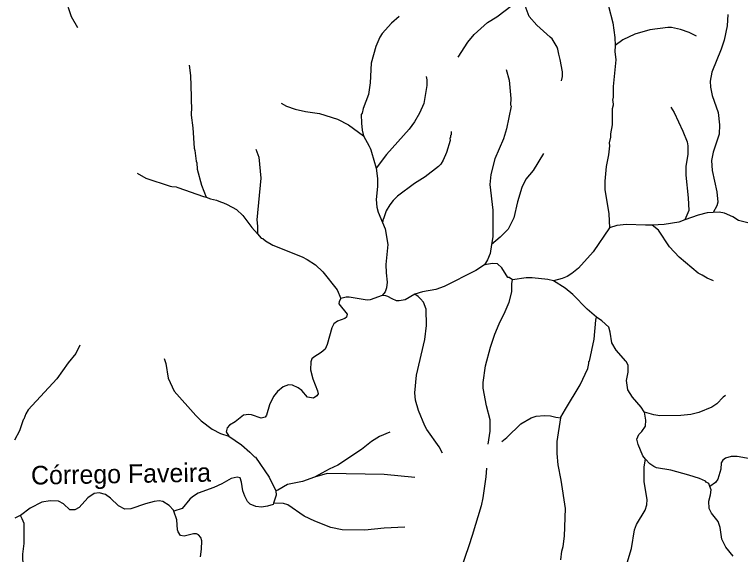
# Model space of a CAD drawing. Extents: x 280.4 to 335.6, y 8893.9 to 8949.5.
# Drawn here: x 280.62 to 288.41, y 8917.81 to 8923.61 of the extents above; entities that cross this region are included whole.
import ezdxf
from ezdxf.enums import TextEntityAlignment as Align

# ---------------------------------------------------------------- set-up
doc = ezdxf.new("R2010")
doc.units = 0
doc.header["$LTSCALE"] = 0.064
doc.linetypes.add('LONG_DASHED', pattern=[7.5, 6, -1.5])
doc.layers.add('61', color=7, linetype='Continuous')
doc.layers.add('7', color=7, linetype='Continuous', lineweight=25)
doc.layers.add('9', color=7, linetype='LONG_DASHED', lineweight=25)

msp = doc.modelspace()

# ---------------------------------------------------------------- linework, layer by layer
at = {"layer": '7'}
for points in [[(285.3795, 8923.1514), (285.4805, 8923.3118), (285.5493, 8923.3936), (285.6944, 8923.5227), (285.7934, 8923.5852), (285.957, 8923.7103), (285.9929, 8923.7477), (286.0681, 8923.8523)], [(286.4884, 8922.8963), (286.4998, 8922.9429), (286.4987, 8922.9917), (286.4747, 8923.1261), (286.46, 8923.1839), (286.4488, 8923.2373), (286.4425, 8923.2565), (286.3867, 8923.346), (286.3675, 8923.366), (286.2226, 8923.4934), (286.1417, 8923.5874), (286.1072, 8923.6723), (286.0681, 8923.8523)], [(286.9295, 8923.8274), (286.9929, 8923.6986), (287.0406, 8923.5202), (287.06, 8923.3621), (287.0645, 8923.2748)], [(284.7434, 8923.587), (284.6639, 8923.5158), (284.5625, 8923.4033), (284.5362, 8923.3654), (284.4934, 8923.2636), (284.4455, 8923.0851), (284.4339, 8922.8753), (284.4147, 8922.7488), (284.3572, 8922.6009), (284.3477, 8922.551), (284.3387, 8922.5336), (284.3395, 8922.4408), (284.3478, 8922.3681), (284.3631, 8922.3063)], [(288.2741, 8923.608), (288.2674, 8923.4875), (288.2332, 8923.3318), (288.2016, 8923.2374), (288.1004, 8922.9907), (288.0838, 8922.8933), (288.0885, 8922.8279), (288.1061, 8922.7385), (288.1697, 8922.5574), (288.1827, 8922.4231), (288.1793, 8922.3248), (288.1148, 8922.1289), (288.0964, 8922.0411), (288.1041, 8921.9323), (288.1571, 8921.7059), (288.1665, 8921.5955), (288.1568, 8921.5543), (288.1175, 8921.4842)], [(287.9374, 8923.3758), (287.8584, 8923.4145), (287.7644, 8923.4488), (287.6691, 8923.4697), (287.6295, 8923.4699), (287.4343, 8923.4427), (287.2759, 8923.3968), (287.1479, 8923.3365), (287.0645, 8923.2748)], [(287.0645, 8923.2748), (287.0646, 8923.2734), (287.0602, 8923.2125), (287.0696, 8923.1229), (287.0441, 8922.835), (287.0425, 8922.7215), (287.0345, 8922.6873), (287.0393, 8922.6815), (287.0409, 8922.6337), (287.033, 8922.5975), (287.0328, 8922.4224), (287.0154, 8922.3271), (287.0147, 8922.2917), (286.9995, 8922.2298), (287.0024, 8922.1978), (286.9929, 8922.1034), (286.9675, 8921.9753), (286.9546, 8921.8187), (286.9546, 8921.7291), (286.9947, 8921.4677), (287.0024, 8921.3169)], [(282.4913, 8923.0641), (282.5053, 8922.9541), (282.5133, 8922.7295), (282.5102, 8922.6726), (282.5165, 8922.6175), (282.5118, 8922.5288), (282.5309, 8922.3929), (282.5451, 8922.1722), (282.553, 8922.148), (282.5649, 8922.0348), (282.5725, 8922.0169), (282.5759, 8921.9491), (282.6236, 8921.7771), (282.6734, 8921.6463)], [(285.8953, 8923.0168), (285.9244, 8922.9028), (285.9438, 8922.7061), (285.9405, 8922.639), (285.9465, 8922.6252), (285.8976, 8922.3814), (285.8651, 8922.2748), (285.7728, 8922.0589), (285.728, 8921.8922), (285.7167, 8921.7852), (285.7517, 8921.5061), (285.7517, 8921.2222), (285.7379, 8921.1397)], [(285.0349, 8922.9427), (285.0434, 8922.9085), (285.0418, 8922.8453), (285.0114, 8922.6538), (284.9624, 8922.5499), (284.9081, 8922.4555), (284.851, 8922.3786), (284.6106, 8922.1042), (284.4986, 8921.958)], [(283.4773, 8922.6553), (283.5363, 8922.6238), (283.6274, 8922.5937), (283.7407, 8922.5663), (283.889, 8922.5458), (284.0832, 8922.4835), (284.2, 8922.4259), (284.3631, 8922.3063)], [(287.6623, 8922.6136), (287.6968, 8922.5561), (287.7912, 8922.3546), (287.8357, 8922.2433), (287.8454, 8922.1978), (287.8437, 8922.1096), (287.8217, 8921.9771), (287.8214, 8921.8851), (287.8469, 8921.6388), (287.8533, 8921.5059), (287.8129, 8921.4034)], [(285.3048, 8922.354), (285.3037, 8922.3161), (285.2977, 8922.3112), (285.2974, 8922.2884), (285.2898, 8922.2818), (285.2911, 8922.2551), (285.2529, 8922.1281), (285.2183, 8922.0464), (285.1908, 8922.0003), (285.1677, 8921.975), (285.0253, 8921.8656), (284.9096, 8921.7927), (284.7278, 8921.6576), (284.6788, 8921.6116), (284.6439, 8921.5658), (284.6069, 8921.5012), (284.578, 8921.4142), (284.5715, 8921.4136), (284.5672, 8921.3752)], [(284.3631, 8922.3063), (284.4223, 8922.1964), (284.4329, 8922.1748), (284.4405, 8922.1544), (284.447, 8922.1323), (284.4986, 8921.958)], [(283.2076, 8922.1615), (283.2391, 8922.0785), (283.2585, 8921.8531), (283.2171, 8921.4046), (283.225, 8921.3374), (283.2251, 8921.2531)], [(286.2959, 8922.1147), (286.184, 8921.9336), (286.1051, 8921.8397), (286.0635, 8921.7517), (286.0164, 8921.597), (285.9771, 8921.4271), (285.9145, 8921.3024), (285.8306, 8921.2169), (285.7379, 8921.1397)], [(284.4986, 8921.958), (284.5108, 8921.8483), (284.5108, 8921.7604), (284.4982, 8921.6225), (284.5067, 8921.5417), (284.5198, 8921.4857), (284.5672, 8921.3752)], [(281.9322, 8921.9066), (282.0236, 8921.852), (282.2881, 8921.7672), (282.3047, 8921.7636), (282.3517, 8921.7571), (282.3694, 8921.7523), (282.6456, 8921.6534), (282.6734, 8921.6463)], [(282.6734, 8921.6463), (282.7212, 8921.6313), (282.7852, 8921.6137), (282.8281, 8921.5985), (282.8588, 8921.5854), (282.8966, 8921.5685), (282.9985, 8921.5135), (283.0651, 8921.4516), (283.1642, 8921.3234), (283.2251, 8921.2531)], [(288.1175, 8921.4842), (288.0509, 8921.4802), (287.9557, 8921.4548), (287.8129, 8921.4034)], [(288.4882, 8921.3735), (288.3874, 8921.3983), (288.3264, 8921.4365), (288.2375, 8921.4765), (288.181, 8921.488), (288.1175, 8921.4842)], [(287.8129, 8921.4034), (287.747, 8921.3796), (287.5885, 8921.3527), (287.4604, 8921.3485)], [(284.5672, 8921.3752), (284.5961, 8921.3078), (284.6227, 8921.1382), (284.6005, 8920.923), (284.6037, 8920.8335), (284.6178, 8920.7356), (284.6101, 8920.6726), (284.5936, 8920.6315), (284.563, 8920.59)], [(287.0024, 8921.3169), (286.8286, 8921.0588), (286.669, 8920.8845), (286.6004, 8920.8275), (286.5489, 8920.7948), (286.4934, 8920.7729), (286.4015, 8920.7489)], [(287.4604, 8921.3485), (287.3888, 8921.3462), (287.1841, 8921.3541), (287.0832, 8921.3446), (287.0024, 8921.3169)], [(288.1212, 8920.7487), (288.0511, 8920.778), (287.9969, 8920.8091), (287.9551, 8920.8331), (287.7515, 8921.0019), (287.6459, 8921.1152), (287.5297, 8921.292), (287.4604, 8921.3485)], [(283.2251, 8921.2531), (283.2644, 8921.2078), (283.2819, 8921.2022), (283.31, 8921.1793), (283.3891, 8921.1331), (283.7023, 8921.0084), (283.7586, 8920.9787), (283.8455, 8920.9207), (283.9266, 8920.8445), (284.0787, 8920.6509), (284.12, 8920.56)], [(285.7379, 8921.1397), (285.7215, 8921.0412), (285.6939, 8920.976), (285.6616, 8920.9215)], [(285.6616, 8920.9215), (285.5688, 8920.8583), (285.228, 8920.6892), (285.1402, 8920.6567), (284.997, 8920.6296), (284.914, 8920.6054)], [(285.9616, 8920.7609), (285.9257, 8920.7834), (285.911, 8920.7861), (285.8462, 8920.8903), (285.7998, 8920.9306), (285.7454, 8920.9366), (285.6616, 8920.9215)], [(286.4015, 8920.7489), (286.3404, 8920.7626), (286.1715, 8920.7815), (286.109, 8920.7796), (285.9616, 8920.7609)], [(285.6989, 8918.9958), (285.7225, 8919.1335), (285.7231, 8919.2564), (285.6814, 8919.4069), (285.6464, 8919.5982), (285.6464, 8919.6572), (285.6708, 8919.837), (285.7256, 8920.0372), (285.7715, 8920.1753), (285.8169, 8920.2876), (285.8837, 8920.42), (285.9263, 8920.52), (285.9532, 8920.6312), (285.9535, 8920.7215), (285.9616, 8920.7609)], [(286.8634, 8920.3602), (286.7621, 8920.4462), (286.6106, 8920.604), (286.5275, 8920.6712), (286.4015, 8920.7489)], [(284.12, 8920.56), (284.1024, 8920.5272), (284.097, 8920.5004), (284.1859, 8920.3903), (284.1788, 8920.3579), (284.1623, 8920.346), (284.0816, 8920.3143), (284.0441, 8920.2872), (284.0221, 8920.2461), (283.9717, 8920.0644), (283.9492, 8920.0141), (283.9089, 8919.9795), (283.8285, 8919.9313), (283.809, 8919.9101), (283.7958, 8919.8788), (283.793, 8919.7925), (283.8198, 8919.6981), (283.8696, 8919.5686)], [(284.563, 8920.59), (284.4328, 8920.5439), (284.4029, 8920.5419), (284.2094, 8920.5737), (284.1774, 8920.5735), (284.12, 8920.56)], [(284.914, 8920.6054), (284.8095, 8920.5454), (284.7455, 8920.5336), (284.7157, 8920.5356), (284.6713, 8920.5559), (284.6245, 8920.5808), (284.6009, 8920.589), (284.563, 8920.59)], [(285.2095, 8918.8995), (285.1739, 8918.9657), (285.0412, 8919.1522), (285.0203, 8919.1906), (284.9536, 8919.3559), (284.9202, 8919.4678), (284.914, 8919.5455), (284.9298, 8919.7348), (285.0194, 8920.1196), (285.0385, 8920.2713), (285.0339, 8920.4434), (285.0079, 8920.5183), (284.9751, 8920.5572), (284.9474, 8920.5818), (284.914, 8920.6054)], [(286.4791, 8919.2786), (286.4802, 8919.2859), (286.532, 8919.3727), (286.6874, 8919.6334), (286.7689, 8919.8096), (286.7815, 8919.8629), (286.7804, 8919.8819), (286.7884, 8919.8864), (286.8392, 8920.122), (286.8554, 8920.3267), (286.8634, 8920.3602)], [(287.3776, 8919.338), (287.3769, 8919.3418), (287.3441, 8919.3939), (287.2515, 8919.4997), (287.201, 8919.5782), (287.1864, 8919.6787), (287.204, 8919.7684), (287.202, 8919.845), (287.1815, 8919.8828), (287.1785, 8919.8862), (287.0735, 8920.0047), (287.028, 8920.0851), (287.0105, 8920.1987), (286.9958, 8920.2505), (286.9225, 8920.3194), (286.8634, 8920.3602)], [(281.3157, 8920.0598), (281.272, 8919.9678), (281.1905, 8919.867), (281.0683, 8919.6979), (280.7602, 8919.3639), (280.7357, 8919.3209), (280.7171, 8919.2636), (280.7074, 8919.2577), (280.6678, 8919.1375), (280.6154, 8919.0369)], [(282.2234, 8919.9155), (282.2399, 8919.8605), (282.2665, 8919.7036), (282.3305, 8919.5653), (282.5602, 8919.3033), (282.6177, 8919.2473), (282.7384, 8919.1566), (282.8259, 8919.1117), (282.9163, 8919.08)], [(283.8696, 8919.5686), (283.8742, 8919.5368), (283.8624, 8919.5128), (283.8256, 8919.4896), (283.7609, 8919.5), (283.7, 8919.5709), (283.6594, 8919.6001), (283.5999, 8919.6282), (283.5563, 8919.6312), (283.5005, 8919.6107), (283.4405, 8919.5592), (283.3966, 8919.506), (283.3546, 8919.419), (283.3216, 8919.3054), (283.3059, 8919.287), (283.265, 8919.2738), (283.1583, 8919.3107), (283.1294, 8919.3149), (283.0755, 8919.3071), (282.9855, 8919.2345), (282.9245, 8919.1983), (282.8984, 8919.1715), (282.8872, 8919.1284), (282.9163, 8919.08)], [(288.2471, 8919.5189), (288.2224, 8919.5004), (288.156, 8919.4291), (288.1007, 8919.3933), (287.9617, 8919.3365), (287.8746, 8919.3157), (287.7677, 8919.3039), (287.5423, 8919.3007), (287.4774, 8919.309), (287.3776, 8919.338)], [(285.8485, 8919.0237), (285.8991, 8919.0657), (286.0494, 8919.2147), (286.1609, 8919.2789), (286.2158, 8919.2948), (286.3035, 8919.3039), (286.3694, 8919.2986), (286.3851, 8919.2973), (286.4258, 8919.2843), (286.4791, 8919.2786)], [(287.3907, 8918.8361), (287.3606, 8918.8695), (287.3096, 8918.9905), (287.2954, 8919.0501), (287.3168, 8919.0981), (287.3496, 8919.1316), (287.3893, 8919.1904), (287.3926, 8919.2534), (287.3776, 8919.338)], [(286.4817, 8917.7536), (286.491, 8917.8458), (286.5052, 8917.8972), (286.5209, 8918.0063), (286.5322, 8918.3059), (286.4846, 8918.6082), (286.452, 8918.7726), (286.4396, 8918.8969), (286.4396, 8919.0249), (286.4791, 8919.2786)], [(282.9163, 8919.08), (283.0533, 8918.9877), (283.1431, 8918.9108), (283.1922, 8918.8577), (283.2012, 8918.8552), (283.3501, 8918.6412), (283.4215, 8918.4954)], [(284.6432, 8919.1257), (284.5327, 8919.0764), (284.4471, 8919.0254), (284.3411, 8918.938), (284.0854, 8918.7682), (283.9944, 8918.7274), (283.8352, 8918.6415)], [(287.3448, 8916.3004), (287.3525, 8916.4237), (287.3447, 8916.5685), (287.3319, 8916.6645), (287.2952, 8916.8068), (287.2714, 8916.8597), (287.2634, 8916.9008), (287.2145, 8917.0285), (287.1687, 8917.1809), (287.1465, 8917.2992), (287.1401, 8917.5006), (287.1496, 8917.5769), (287.2391, 8917.8742), (287.2714, 8918.0763), (287.2928, 8918.1346), (287.3875, 8918.2861), (287.4022, 8918.3436), (287.4086, 8918.4026), (287.3737, 8918.5899), (287.3737, 8918.7512), (287.3907, 8918.8361)], [(288.0805, 8918.5419), (288.0677, 8918.5726), (288.0391, 8918.5879), (288.0325, 8918.5976), (287.9701, 8918.6251), (287.8541, 8918.6639), (287.6607, 8918.7155), (287.5086, 8918.7424), (287.4775, 8918.7551), (287.4376, 8918.784), (287.3907, 8918.8361)], [(288.5619, 8918.8257), (288.5512, 8918.8297), (288.3754, 8918.8636), (288.309, 8918.8621), (288.2469, 8918.8448), (288.2212, 8918.8239), (288.2035, 8918.7944), (288.1985, 8918.7275), (288.1673, 8918.6209), (288.1415, 8918.5846), (288.0805, 8918.5419)], [(285.6819, 8918.7372), (285.6753, 8918.6464), (285.643, 8918.418), (285.6238, 8918.3316), (285.5296, 8918.0155), (285.4917, 8917.9037), (285.3613, 8917.5185), (285.2831, 8917.3465), (285.1926, 8917.2195)], [(284.9126, 8918.6374), (284.5838, 8918.6705), (283.9703, 8918.68), (283.8352, 8918.6415)], [(283.3961, 8918.3636), (283.3911, 8918.3485), (283.3298, 8918.3311), (283.2682, 8918.3204), (283.2051, 8918.3254), (283.1459, 8918.3505), (283.1167, 8918.3806), (283.0864, 8918.4364), (283.0651, 8918.4954), (283.051, 8918.589), (283.0366, 8918.6326), (283.0074, 8918.6415), (282.9411, 8918.6276), (282.8417, 8918.57), (282.7554, 8918.5297), (282.5886, 8918.4706), (282.5252, 8918.431), (282.4986, 8918.4063), (282.4154, 8918.3029), (282.3264, 8918.2764)], [(283.8352, 8918.6415), (283.7064, 8918.595), (283.5475, 8918.5631), (283.443, 8918.5014), (283.4215, 8918.4954)], [(288.3303, 8917.7921), (288.2532, 8917.8902), (288.2105, 8917.975), (288.1926, 8918.0996), (288.1686, 8918.1645), (288.098, 8918.2563), (288.0742, 8918.306), (288.0677, 8918.3842), (288.0877, 8918.4509), (288.0961, 8918.5043), (288.0805, 8918.5419)], [(282.3264, 8918.2764), (282.3231, 8918.2863), (282.2739, 8918.3359), (282.209, 8918.381), (282.1699, 8918.3858), (282.1144, 8918.3794), (282.0225, 8918.3555), (281.8631, 8918.2998), (281.8014, 8918.2992), (281.733, 8918.3316), (281.6471, 8918.4142), (281.592, 8918.4537), (281.5234, 8918.4737), (281.4706, 8918.4646), (281.4011, 8918.4195), (281.3112, 8918.3143), (281.2637, 8918.2892), (281.2091, 8918.2915), (281.1396, 8918.3539), (281.0892, 8918.3827), (280.9991, 8918.3887)], [(283.4215, 8918.4954), (283.4243, 8918.4482), (283.3961, 8918.3636)], [(280.9991, 8918.3887), (280.9077, 8918.3718), (280.7823, 8918.3092), (280.6789, 8918.2298)], [(284.8048, 8918.1037), (284.5851, 8918.0932), (284.3759, 8918.0709), (284.1327, 8918.0742), (284.0131, 8918.0997), (283.8398, 8918.1675), (283.7266, 8918.2232), (283.5489, 8918.343), (283.5026, 8918.3588), (283.3961, 8918.3636)], [(282.6126, 8917.787), (282.6239, 8917.8671), (282.6251, 8917.9573), (282.614, 8917.9923), (282.5912, 8918.0226), (282.5698, 8918.0324), (282.5366, 8918.0339), (282.4351, 8918.007), (282.3987, 8918.0135), (282.3712, 8918.0532), (282.3639, 8918.0758), (282.3582, 8918.1812), (282.3264, 8918.2764)], [(280.6789, 8918.2298), (280.6694, 8918.2253), (280.6204, 8918.2021)], [(280.6307, 8916.4643), (280.6616, 8916.5354), (280.7104, 8916.609), (280.7099, 8916.6186), (280.7221, 8916.6317), (280.7589, 8916.7152), (280.794, 8916.8347), (280.8037, 8916.9217), (280.8037, 8917.0354), (280.7906, 8917.1528), (280.7654, 8917.296), (280.7557, 8917.5248), (280.7193, 8917.6687), (280.7047, 8917.7566), (280.7047, 8917.814), (280.7174, 8917.9286), (280.7206, 8918.1448), (280.6985, 8918.1933), (280.6789, 8918.2298)]]:
    msp.add_lwpolyline(points, dxfattribs=at)
at = {"layer": '9'}
msp.add_lwpolyline([(281.2941, 8923.467), (281.2278, 8923.5835), (281.194, 8923.6794), (281.1814, 8923.737), (281.1825, 8923.796), (281.1687, 8923.8436), (281.1779, 8923.9065), (281.1812, 8924), (281.1699, 8924.1321), (281.0991, 8924.319), (281.0567, 8924.4954), (281.0565, 8924.6767), (281.0675, 8924.8409), (281.0626, 8924.9013), (281.0381, 8924.9859), (280.96, 8925.1223), (280.9169, 8925.2507), (280.8969, 8925.3867), (280.9954, 8925.7471)], dxfattribs=at)

# ---------------------------------------------------------------- texts
at = {"layer": '61'}
msp.add_text('Córrego Faveira', height=0.2, rotation=0.956, dxfattribs=at).set_placement((281.7601, 8918.5771), align=Align.CENTER)

doc.saveas('drawing.dxf')
